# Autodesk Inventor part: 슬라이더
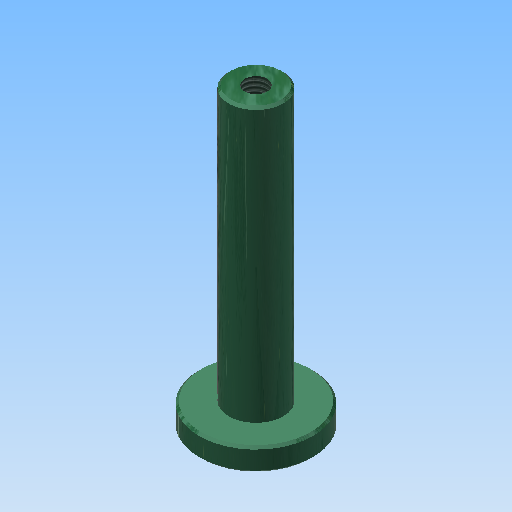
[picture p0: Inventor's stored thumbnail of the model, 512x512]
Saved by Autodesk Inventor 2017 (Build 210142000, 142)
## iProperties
Created: 2016-02
Part Number: 슬라이더
Material: 스테인리스강
Document SubType Name: Modeling
Designer: mduedu
Density: 8.08 g/cm^3
Appearance: 매끄러움 - 짙은 바다 녹색
Mass: 72.5507 g
Surface Area: 37.669 cm^2
Volume: 8.97904 cm^3
Author: mduedu
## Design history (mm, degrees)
sketch "스케치1"
  geometry: C1 r 12.5 at (0, 0); 1 further point
  constraints: 1 centre point, 1 coincident
  dimensions: "d0" = 25 diameter of C1
extrude "돌출1" new body sketch "스케치1" distance "d1" = 5; taper "d2" = 0 deg
sketch "스케치2"
  geometry: C1 r 6 at (0, 0); 1 further point
  constraints: 1 centre point, 1 coincident
  dimensions: "d3" = 12 diameter of C1
extrude "돌출2" join sketch "스케치2" distance "d4" = 60; taper "d5" = 0 deg
chamfer "모따기1" distance "d6" = 0.5; stored, may be unused: second distance "d7" = 2, angle "d8" = 45 deg
hole "구멍1" diameter "d11" = 4.917; stored, may be unused: countersink angle "d15" = 90 deg, drill point angle "d17" = 118 deg; dims "d9" = 10, "d10" = 10, "d12" = 10, "d13" = 4, "d14" = 2, "d16" = 12
chamfer "모따기2" distance "d18" = 0.5; stored, may be unused: second distance "d19" = 2, angle "d20" = 45 deg
sketch "스케치3"
  geometry: L1 (-12.5, 4.5)-(-12, 5) reference; L2 (-12, 5)-(-6, 5) reference; L3 (-6, 5)-(-6, 64.5) reference; L4 (-6, 64.5)-(-5.5, 65) reference; L5 (-5.5, 65)-(-2.458, 65) reference; L6 (-2.458, 65)-(-2.458, 53) reference; L7 (-2.458, 53)-(0, 51.523) reference; L8 (0, 51.523)-(2.458, 53) reference; L9 (2.458, 53)-(2.458, 65) reference; L10 (2.458, 65)-(5.5, 65) reference; L11 (5.5, 65)-(6, 64.5) reference; L12 (6, 64.5)-(6, 5) reference; L13 (6, 5)-(12, 5) reference; L14 (12, 5)-(12.5, 4.5) reference; L15 (12.5, 4.5)-(12.5, 0.5) reference; L16 (12.5, 0.5)-(12, 0) reference; L17 (12, 0)-(-12, 0) reference; L18 (-12, 0)-(-12.5, 0.5) reference; L19 (-12.5, 0.5)-(-12.5, 4.5) reference; 1 further point
  node "절단 모서리 투영1"
node "솔리드1"
